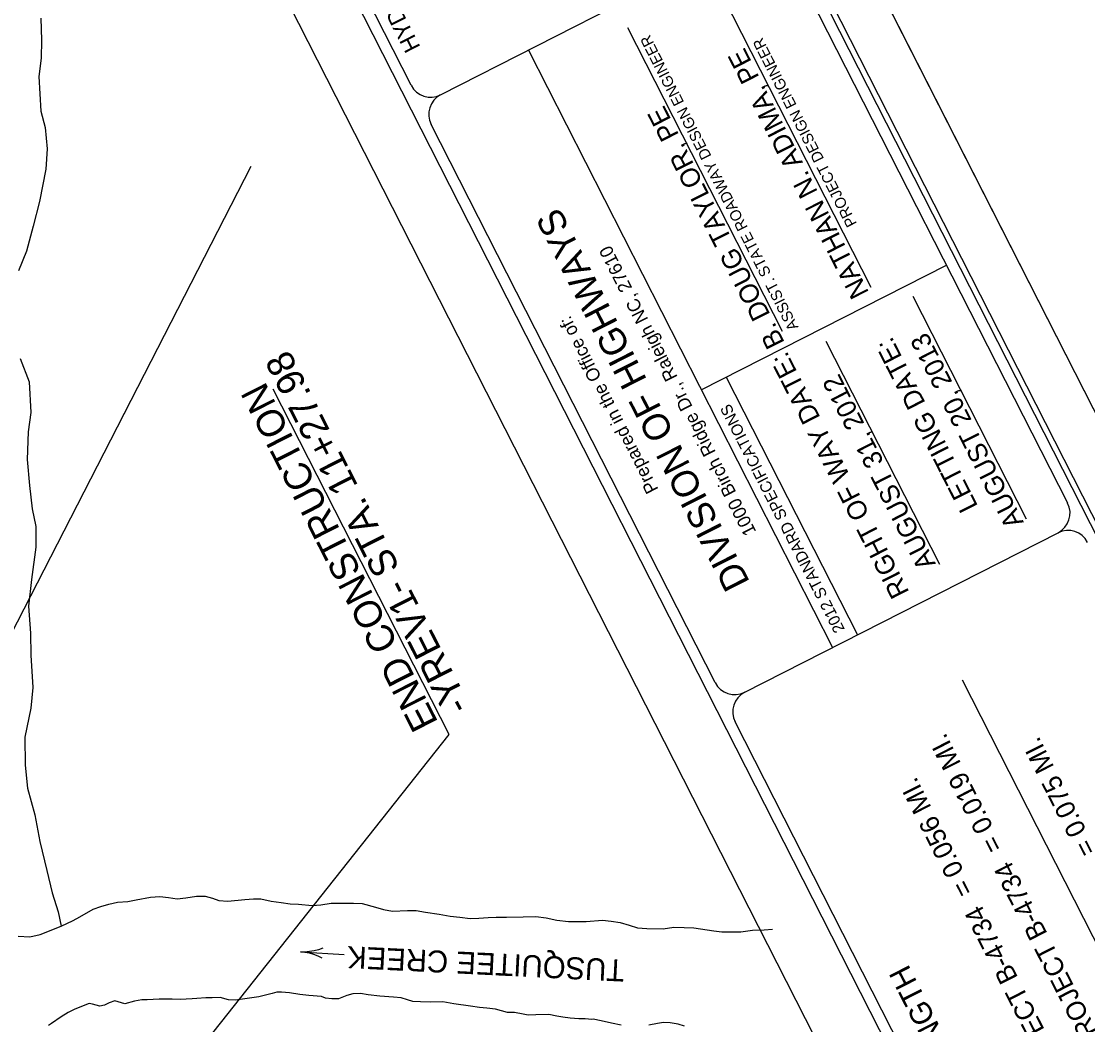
# Model space of a CAD drawing. Extents: x 558484 to 564063, y 513718 to 518374.
# Drawn here: x 559446.5 to 559931.7, y 515539 to 515995.6 of the extents above; entities that cross this region are included whole.
import ezdxf

# ---------------------------------------------------------------- set-up
doc = ezdxf.new("R2010")
doc.units = 0
for name, color, linetype in [('COGO Default Parcel', 7, 'Continuous'), ('Default', 7, 'Continuous'), ('Prop Dimension', 7, 'Continuous'), ('Prop DSN Text', 7, 'Continuous'), ('Sheet Cutting Line CELL', 7, 'Continuous'), ('Sheet Data Field CELL', 7, 'Continuous'), ('Sheet Plot Border Inside CELL', 7, 'Continuous'), ('Sheet Plot Border Outside CELL', 7, 'Continuous'), ('Sheet Title CELL', 7, 'Continuous')]:
    doc.layers.add(name, color=color, linetype=linetype)

# ---------------------------------------------------------------- blocks, each defined once
blk = doc.blocks.new('EXIST HYDRO RIVER FLOW ARROW')
at = {"layer": 'Default'}
for p, q in [((0.2, 0), (-0.2, 0)), ((0, 0.04575), (0.03775, 0.03)), ((0, 0), (0, 0)), ((0.03775, 0.03), (0.07725, 0.01725)), ((0.07725, 0.01725), (0.118, 0.00775)), ((0.118, 0.00775), (0.159, 0.0015)), ((0.159, 0.0015), (0.2, 0)), ((0.159, -0.0015), (0.2, 0)), ((0, -0.04575), (0.03775, -0.03)), ((0.03775, -0.03), (0.07725, -0.01725)), ((0.07725, -0.01725), (0.118, -0.00775)), ((0.118, -0.00775), (0.159, -0.0015))]:
    blk.add_line(p, q, dxfattribs=at)

msp = doc.modelspace()

# ---------------------------------------------------------------- linework, layer by layer
at = {"layer": 'COGO Default Parcel'}
msp.add_line((559363.44, 515564.02), (559551.08, 515929.67), dxfattribs=at)
at = {"layer": 'Default'}
msp.add_lwpolyline([(559444.47, 516246.59), (559867.25, 515416.18), (559371.15, 515163.61), (558948.37, 515994.01)], close=True, dxfattribs=at)
for points in [[(559455.34, 515996.94), (559455.67, 515987.05), (559455.44, 515978.81), (559454.5, 515970.43), (559455.34, 515954.61), (559457.28, 515947.3), (559458.25, 515937.52), (559457.61, 515928.25), (559454.8, 515913.54), (559451.84, 515902.3), (559448.78, 515890.97), (559445.14, 515881.97)], [(559445.87, 515842.19), (559450.1, 515831.49), (559450.81, 515817.5), (559449.64, 515808.77), (559449.18, 515796.21), (559450.2, 515784.29), (559451.45, 515773.81), (559453.13, 515765.74), (559453.04, 515756.36), (559451.11, 515741.63), (559449.79, 515729.53), (559450.6, 515717.1), (559450.74, 515707.23), (559451.69, 515692.41), (559450.75, 515683.1), (559448.1, 515669.89), (559448.21, 515657.11), (559449.3, 515646.67), (559452.58, 515634.56), (559454.92, 515622.4), (559458.09, 515609.12), (559460.54, 515599.09), (559463.27, 515590.41), (559464.58, 515583.81)], [(559445.07, 515579.35), (559450.39, 515578.99), (559455.04, 515580.01), (559464.58, 515583.81), (559470.12, 515586.37), (559473.02, 515588.11), (559479.11, 515591.58), (559482.6, 515592.79), (559486.29, 515593.81), (559490.21, 515594.72), (559494.94, 515595.16), (559498.68, 515595.91), (559505.21, 515597.05), (559509.47, 515597.31), (559513.51, 515596.93), (559517.31, 515596.31), (559521.37, 515596.74), (559526.25, 515597.46), (559530.14, 515597.47), (559533.4, 515596.61), (559536.37, 515595.51), (559540.38, 515595.22), (559548.1, 515595.95), (559552.09, 515596.29), (559555.41, 515596.29), (559560.13, 515595.21), (559564.64, 515594.65), (559568.79, 515594.02), (559572.55, 515593.84), (559578.84, 515593.24), (559582.7, 515593.55), (559587.49, 515594.26), (559591.9, 515594.4), (559597.65, 515594.35), (559601.62, 515594.11), (559607.63, 515592.57), (559611.27, 515591.38), (559615.34, 515590.71), (559622.15, 515590.92), (559626.2, 515591.02), (559630.36, 515590.26), (559636.55, 515589.34), (559641.62, 515588.44), (559645.97, 515587.9), (559650.73, 515587.31), (559654.69, 515587.44), (559658.86, 515587.82), (559662.49, 515587.89), (559667.26, 515587.93), (559674.9, 515588.15), (559680.6, 515588.29), (559685.23, 515587.61), (559690.14, 515586.52), (559695.47, 515585.99), (559703.55, 515586.05), (559710.97, 515586.53), (559714.87, 515586.14), (559718.91, 515585.54), (559723.02, 515584.32), (559726.93, 515583.08), (559731.1, 515582.78), (559738.57, 515582.68), (559743.4, 515583.48), (559748.05, 515583.19), (559752.56, 515583.04), (559761.6, 515581.76), (559765.21, 515581.32), (559773.95, 515581.21), (559779.26, 515582.03), (559784.45, 515582.21), (559788.3, 515582.5)], [(559719.5, 515538.84), (559715.08, 515539.71), (559710.38, 515540.75), (559706.76, 515541.49), (559706.1, 515541.42), (559703.02, 515541.69), (559700.1, 515541.77), (559696.23, 515541.93), (559692.92, 515542.46), (559690.21, 515542.92), (559686.47, 515543.65), (559680.64, 515543.5), (559677.09, 515543.39), (559674.9, 515543.79), (559670.84, 515544.64), (559667.77, 515544.65), (559664.91, 515545.27), (559662.32, 515546.03), (559658.24, 515546.54), (559655.01, 515546.87), (559650.93, 515547.43), (559643.24, 515548.56), (559638.3, 515549.38), (559632.7, 515549.35), (559628.14, 515549.47), (559624.64, 515549.66), (559622.25, 515550.32), (559619.37, 515551.21), (559615.89, 515551.62), (559609.66, 515551.94), (559604.28, 515552.67), (559600.8, 515553.22), (559597.28, 515553.14), (559594.54, 515552.33), (559590.82, 515550.79), (559587.71, 515550.75), (559584.91, 515551.12), (559582.99, 515551.84), (559577.28, 515552.24), (559573.18, 515552.73), (559568.53, 515553.58), (559564.9, 515553.84), (559562.7, 515553.88), (559560.63, 515553.27), (559554.62, 515551.66), (559550.31, 515551.05), (559543.93, 515550.2), (559540.77, 515550.33), (559536.98, 515551.41), (559533.29, 515551.32), (559530.42, 515551.21), (559526.39, 515550.88), (559524.18, 515550.86), (559518.78, 515550.55), (559515.08, 515550.62), (559509.22, 515550.67), (559503.8, 515550.39), (559501.35, 515550.31), (559497.95, 515549.68), (559493.61, 515548.58), (559489.06, 515549.88)], [(559489.06, 515549.88), (559486.49, 515548.98), (559484.33, 515547.92), (559482.13, 515547.49), (559478.81, 515548.31), (559477.36, 515548.66), (559470.8, 515546.13), (559467.76, 515544.62), (559464.67, 515542.63), (559460.19, 515539.61), (559458.76, 515538.59)], [(559748.26, 515538.3), (559745.44, 515539.21), (559741.74, 515539.87), (559738.7, 515540.06), (559736, 515539.64), (559731.95, 515538.77)]]:
    msp.add_lwpolyline(points, dxfattribs=at)
at = {"layer": 'Prop Dimension'}
msp.add_line((559507.12, 515501.93), (559641.09, 515671.03), dxfattribs=at)
at = {"layer": 'Prop DSN Text'}
msp.add_line((559641.09, 515671.03), (559561.1, 515828.14), dxfattribs=at)
at = {"layer": 'Sheet Cutting Line CELL'}
msp.add_line((560390.41, 514923.75), (559626.36, 516424.45), dxfattribs=at)
at = {"layer": 'Sheet Data Field CELL'}
msp.add_line((560022.2, 515406.12), (559874.72, 515695.79), dxfattribs=at)
at = {"layer": 'Sheet Plot Border Inside CELL'}
msp.add_lwpolyline([(560364.51, 514925.16), (559608.41, 516410.26), (558668.16, 515931.55), (559424.26, 514446.45)], close=True, dxfattribs=at)
at = {"layer": 'Sheet Plot Border Outside CELL'}
msp.add_lwpolyline([(558646.11, 515925.37), (559410.15, 514424.68), (560390.41, 514923.75), (559626.36, 516424.45)], close=True, dxfattribs=at)
at = {"layer": 'Sheet Title CELL'}
for p, q in [((560093.55, 515032.95), (559449.28, 516298.38)), ((559623.88, 515966.47), (559533.24, 516144.5)), ((559779.92, 516034.7), (559637.34, 515962.1)), ((559833.13, 515874.5), (559762.24, 516013.74)), ((559792.87, 515854.4), (559722.49, 515992.66)), ((559677.22, 515982.41), (559815.59, 515710.6)), ((559762.26, 515694.67), (559632.95, 515948.65)), ((559755.9, 515827.83), (559867.52, 515884.66)), ((559852.19, 515870.57), (559903.8, 515769.2)), ((559812.63, 515849.98), (559864.24, 515748.61)), ((559767.28, 515833.62), (559826.95, 515716.38)), ((559784.46, 515799.84), (559784.46, 515799.84)), ((559838.46, 515799.28), (559838.46, 515799.28)), ((559775.71, 515690.3), (559918.29, 515762.89)), ((559943.76, 515338.22), (559771.35, 515676.85))]:
    msp.add_line(p, q, dxfattribs=at)
for points in [[(560287.83, 515070.15), (559616.34, 516389.05)], [(559922.67, 515776.34), (559793.37, 516030.32)]]:
    msp.add_lwpolyline(points, dxfattribs=at)
for centre, start, end in [((559632.75, 515970.99), 206.9819, 296.9819), ((559641.82, 515953.17), 116.9819, 206.9819), ((559913.71, 515771.78), 296.9819, 26.9819), ((559922.79, 515753.96), 26.9819, 116.9819), ((559771.13, 515699.19), 206.9819, 296.9819), ((559780.2, 515681.37), 116.9819, 206.9819)]:
    msp.add_arc(centre, 10, start, end, dxfattribs=at)

# ---------------------------------------------------------------- block references
at = {"layer": 'Default', "xscale": 49.99999999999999, "yscale": 50, "rotation": 176.45585277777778}
msp.add_blockref('EXIST HYDRO RIVER FLOW ARROW', (559583.47, 515571.53), dxfattribs=at)

# ---------------------------------------------------------------- texts
at = {"layer": 'Default'}
for s, height, rotation, p in [('-YREV1- STA. 11+27.98', 12.5, 116.9819, (559650.92, 515684)), ('END CONSTRUCTION', 12.5, 116.9819, (559636.32, 515676.57)), ('TUSQUITEE CREEK', 10, 177.1845, (559721.11, 515568.6))]:
    msp.add_text(s, height=height, rotation=rotation, dxfattribs=at).set_placement(p)
at = {"layer": 'Sheet Data Field CELL'}
for s, rotation, p in [('     NATHAN N. ADIMA, PE    ', 116.9819, (559839.73, 515857.67)), ('   B. DOUG TAYLOR, PE       ', 116.9819, (559798.41, 515840.68)), ('AUGUST 20, 2013   ', 116.9819, (559902.72, 515767.61)), ('AUGUST 31, 2012   ', 116.9819, (559862.74, 515748.74)), ('LENGTH STRUCTURE TIP PROJECT B-4734  = 0.019 MI.', 116.9628, (560006.74, 515397.3)), ('TOTAL LENGTH TIP PROJECT B-4734      = 0.075 MI.', 116.9628, (560039.44, 515414.83)), ('LENGTH ROADWAY TIP PROJECT B-4734  = 0.056 MI.', 116.9628, (559988.05, 515387.73))]:
    msp.add_text(s, height=8.7501, rotation=rotation, dxfattribs=at).set_placement(p)
at = {"layer": 'Sheet Title CELL'}
for s, height, p in [(' HYDRAULICS ENGINEER', 7.5, (559629.51, 515981.34)), ('ASSIST. STATE ROADWAY DESIGN ENGINEER', 4.9995, (559800.26, 515856.42)), ('PROJECT DESIGN ENGINEER', 4.9995, (559826.85, 515903.51)), ('DIVISION OF HIGHWAYS', 12.1872, (559778.21, 515740.37)), ('1000 Birch Ridge Dr., Raleigh NC, 27610', 6, (559781.05, 515763.33)), ('Prepared in the Office of:', 5.9994, (559736.54, 515782.57)), ('LETTING DATE:', 8.7498, (559881.98, 515774.92)), ('RIGHT OF WAY DATE: ', 8.7498, (559850.67, 515735.81)), ('2012 STANDARD SPECIFICATIONS', 5.2, (559821.32, 515718.95)), ('PROJECT LENGTH', 9.9996, (559904.49, 515459.73))]:
    msp.add_text(s, height=height, rotation=116.9819, dxfattribs=at).set_placement(p)

doc.saveas('drawing.dxf')
